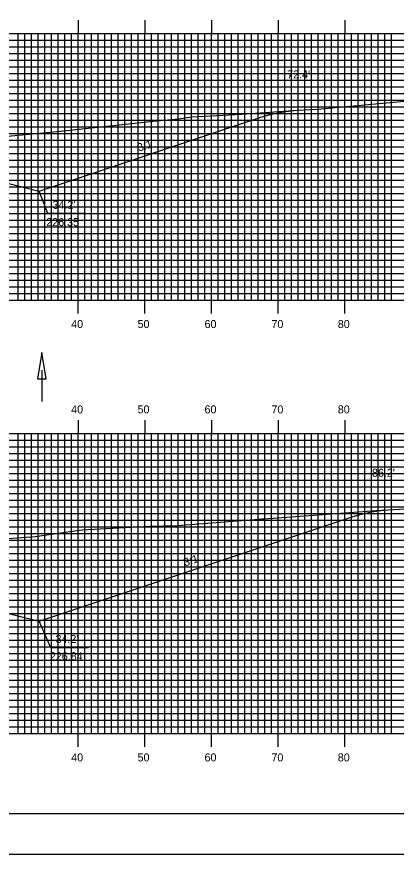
# Model space of a CAD drawing. Extents: x 1818457 to 1818800, y 442591 to 442811.
# Drawn here: x 1818653.4 to 1818710.4, y 442590.5 to 442716.2 of the extents above; entities that cross this region are included whole.
import ezdxf

# ---------------------------------------------------------------- set-up
doc = ezdxf.new("R2010")
doc.units = 0
for name, color, linetype in [('ANNOTATION', 7, 'Continuous'), ('BORDER', 7, 'Continuous'), ('D_Drainage_Ditch_Line', 7, 'Continuous'), ('D_Roadway_Centerline', 7, 'Continuous'), ('D_Roadway_SlopeLines', 7, 'Continuous'), ('D_Text_Standard', 7, 'Continuous'), ('H_V ANNOTATION', 7, 'Continuous'), ('MAJOR', 7, 'Continuous'), ('MINOR', 7, 'Continuous'), ('PLOT BOUNDARY', 7, 'Continuous'), ('S_Roadway_Centerline', 7, 'Continuous')]:
    doc.layers.add(name, color=color, linetype=linetype)

msp = doc.modelspace()

# ---------------------------------------------------------------- linework, layer by layer
at = {"layer": 'ANNOTATION'}
for points in [[(1818663.78, 442686.63), (1818658.09, 442686.63), (1818656.81, 442690.02)], [(1818664.23, 442621.52), (1818658.54, 442621.52), (1818656.81, 442625.5)]]:
    msp.add_lwpolyline(points, dxfattribs=at)
at = {"layer": 'BORDER'}
msp.add_lwpolyline([(1818473.04, 442596.67), (1818793.04, 442596.67), (1818793.04, 442806.67), (1818473.04, 442806.67)], close=True, dxfattribs=at)
at = {"layer": 'D_Drainage_Ditch_Line'}
msp.add_line((1818657.21, 442663.17), (1818657.21, 442658.47), dxfattribs=at)
msp.add_lwpolyline([(1818656.55, 442661.86), (1818657.87, 442661.86), (1818657.21, 442665.8)], close=True, dxfattribs=at)
at = {"layer": 'D_Roadway_Centerline'}
for points in [[(1818584.45, 442689.01), (1818590.64, 442690.56), (1818592.46, 442691.02), (1818602.64, 442693.56), (1818610.64, 442693.88), (1818622.64, 442694.12), (1818634.64, 442693.88), (1818642.64, 442693.56), (1818652.81, 442691.02), (1818656.81, 442690.02), (1818690.05, 442701.1), (1818691.3, 442701.47), (1818692.55, 442701.76), (1818693.8, 442701.97), (1818695.05, 442702.1)], [(1818576.1, 442628.49), (1818577.35, 442628.57), (1818578.6, 442628.51), (1818579.85, 442628.3), (1818581.1, 442627.96), (1818588.46, 442625.5), (1818592.46, 442626.5), (1818602.64, 442629.05), (1818610.64, 442629.37), (1818622.64, 442629.61), (1818634.64, 442629.37), (1818642.64, 442629.05), (1818652.81, 442626.5), (1818656.81, 442625.5), (1818703.88, 442641.19), (1818705.13, 442641.57), (1818706.38, 442641.86), (1818707.63, 442642.06), (1818708.88, 442642.19)]]:
    msp.add_lwpolyline(points, dxfattribs=at)
at = {"layer": 'D_Roadway_SlopeLines'}
for points in [[(1818656.81, 442690.02), (1818690.05, 442701.1), (1818691.3, 442701.47), (1818692.55, 442701.76), (1818693.8, 442701.97), (1818695.05, 442702.1)], [(1818642.64, 442693.56), (1818656.81, 442690.02)], [(1818656.81, 442625.5), (1818703.88, 442641.19), (1818705.13, 442641.57), (1818706.38, 442641.86), (1818707.63, 442642.06), (1818708.88, 442642.19)], [(1818642.64, 442629.05), (1818656.81, 442625.5)]]:
    msp.add_lwpolyline(points, dxfattribs=at)
at = {"layer": 'MAJOR'}
for p, q in [((1818662.64, 442715.67), (1818662.64, 442713.67)), ((1818672.64, 442715.67), (1818672.64, 442713.67)), ((1818682.64, 442715.67), (1818682.64, 442713.67)), ((1818692.64, 442715.67), (1818692.64, 442713.67)), ((1818702.64, 442715.67), (1818702.64, 442713.67)), ((1818482.64, 442713.67), (1818762.64, 442713.67)), ((1818482.64, 442713.67), (1818762.64, 442713.67)), ((1818662.64, 442673.67), (1818662.64, 442713.67)), ((1818672.64, 442673.67), (1818672.64, 442713.67)), ((1818682.64, 442673.67), (1818682.64, 442713.67)), ((1818692.64, 442673.67), (1818692.64, 442713.67)), ((1818702.64, 442673.67), (1818702.64, 442713.67)), ((1818482.64, 442708.67), (1818762.64, 442708.67)), ((1818482.64, 442703.67), (1818762.64, 442703.67)), ((1818482.64, 442698.67), (1818762.64, 442698.67)), ((1818482.64, 442693.67), (1818762.64, 442693.67)), ((1818482.64, 442688.67), (1818762.64, 442688.67)), ((1818482.64, 442683.67), (1818762.64, 442683.67)), ((1818482.64, 442678.67), (1818762.64, 442678.67)), ((1818482.64, 442673.67), (1818762.64, 442673.67)), ((1818482.64, 442673.67), (1818762.64, 442673.67)), ((1818662.64, 442671.66), (1818662.64, 442673.67)), ((1818672.64, 442671.66), (1818672.64, 442673.67)), ((1818682.64, 442671.66), (1818682.64, 442673.67)), ((1818692.64, 442671.66), (1818692.64, 442673.67)), ((1818702.64, 442671.66), (1818702.64, 442673.67)), ((1818662.64, 442655.67), (1818662.64, 442653.67)), ((1818672.64, 442655.67), (1818672.64, 442653.67)), ((1818682.64, 442655.67), (1818682.64, 442653.67)), ((1818692.64, 442655.67), (1818692.64, 442653.67)), ((1818702.64, 442655.67), (1818702.64, 442653.67)), ((1818482.64, 442653.67), (1818762.64, 442653.67)), ((1818482.64, 442653.67), (1818762.64, 442653.67)), ((1818662.64, 442608.67), (1818662.64, 442653.67)), ((1818672.64, 442608.67), (1818672.64, 442653.67)), ((1818682.64, 442608.67), (1818682.64, 442653.67)), ((1818692.64, 442608.67), (1818692.64, 442653.67)), ((1818702.64, 442608.67), (1818702.64, 442653.67)), ((1818482.64, 442648.67), (1818762.64, 442648.67)), ((1818482.64, 442643.67), (1818762.64, 442643.67)), ((1818482.64, 442638.67), (1818762.64, 442638.67)), ((1818482.64, 442633.67), (1818762.64, 442633.67)), ((1818482.64, 442628.67), (1818762.64, 442628.67)), ((1818482.64, 442623.67), (1818762.64, 442623.67)), ((1818482.64, 442618.67), (1818762.64, 442618.67)), ((1818482.64, 442613.67), (1818762.64, 442613.67)), ((1818482.64, 442608.67), (1818762.64, 442608.67)), ((1818482.64, 442608.67), (1818762.64, 442608.67)), ((1818662.64, 442606.66), (1818662.64, 442608.67)), ((1818672.64, 442606.66), (1818672.64, 442608.67)), ((1818682.64, 442606.66), (1818682.64, 442608.67)), ((1818692.64, 442606.66), (1818692.64, 442608.67)), ((1818702.64, 442606.66), (1818702.64, 442608.67))]:
    msp.add_line(p, q, dxfattribs=at)
at = {"layer": 'MINOR'}
for p, q in [((1818653.64, 442673.67), (1818653.64, 442713.67)), ((1818654.64, 442673.67), (1818654.64, 442713.67)), ((1818655.64, 442673.67), (1818655.64, 442713.67)), ((1818656.64, 442673.67), (1818656.64, 442713.67)), ((1818657.64, 442673.67), (1818657.64, 442713.67)), ((1818658.64, 442673.67), (1818658.64, 442713.67)), ((1818659.64, 442673.67), (1818659.64, 442713.67)), ((1818660.64, 442673.67), (1818660.64, 442713.67)), ((1818661.64, 442673.67), (1818661.64, 442713.67)), ((1818663.64, 442673.67), (1818663.64, 442713.67)), ((1818664.64, 442673.67), (1818664.64, 442713.67)), ((1818665.64, 442673.67), (1818665.64, 442713.67)), ((1818666.64, 442673.67), (1818666.64, 442713.67)), ((1818667.64, 442673.67), (1818667.64, 442713.67)), ((1818668.64, 442673.67), (1818668.64, 442713.67)), ((1818669.64, 442673.67), (1818669.64, 442713.67)), ((1818670.64, 442673.67), (1818670.64, 442713.67)), ((1818671.64, 442673.67), (1818671.64, 442713.67)), ((1818673.64, 442673.67), (1818673.64, 442713.67)), ((1818674.64, 442673.67), (1818674.64, 442713.67)), ((1818675.64, 442673.67), (1818675.64, 442713.67)), ((1818676.64, 442673.67), (1818676.64, 442713.67)), ((1818677.64, 442673.67), (1818677.64, 442713.67)), ((1818678.64, 442673.67), (1818678.64, 442713.67)), ((1818679.64, 442673.67), (1818679.64, 442713.67)), ((1818680.64, 442673.67), (1818680.64, 442713.67)), ((1818681.64, 442673.67), (1818681.64, 442713.67)), ((1818683.64, 442673.67), (1818683.64, 442713.67)), ((1818684.64, 442673.67), (1818684.64, 442713.67)), ((1818685.64, 442673.67), (1818685.64, 442713.67)), ((1818686.64, 442673.67), (1818686.64, 442713.67)), ((1818687.64, 442673.67), (1818687.64, 442713.67)), ((1818688.64, 442673.67), (1818688.64, 442713.67)), ((1818689.64, 442673.67), (1818689.64, 442713.67)), ((1818690.64, 442673.67), (1818690.64, 442713.67)), ((1818691.64, 442673.67), (1818691.64, 442713.67)), ((1818693.64, 442673.67), (1818693.64, 442713.67)), ((1818694.64, 442673.67), (1818694.64, 442713.67)), ((1818695.64, 442673.67), (1818695.64, 442713.67)), ((1818696.64, 442673.67), (1818696.64, 442713.67)), ((1818697.64, 442673.67), (1818697.64, 442713.67)), ((1818698.64, 442673.67), (1818698.64, 442713.67)), ((1818699.64, 442673.67), (1818699.64, 442713.67)), ((1818700.64, 442673.67), (1818700.64, 442713.67)), ((1818701.64, 442673.67), (1818701.64, 442713.67)), ((1818703.64, 442673.67), (1818703.64, 442713.67)), ((1818704.64, 442673.67), (1818704.64, 442713.67)), ((1818705.64, 442673.67), (1818705.64, 442713.67)), ((1818706.64, 442673.67), (1818706.64, 442713.67)), ((1818707.64, 442673.67), (1818707.64, 442713.67)), ((1818708.64, 442673.67), (1818708.64, 442713.67)), ((1818709.64, 442673.67), (1818709.64, 442713.67)), ((1818482.64, 442712.67), (1818762.64, 442712.67)), ((1818482.64, 442711.67), (1818762.64, 442711.67)), ((1818482.64, 442710.67), (1818762.64, 442710.67)), ((1818482.64, 442709.67), (1818762.64, 442709.67)), ((1818482.64, 442707.67), (1818762.64, 442707.67)), ((1818482.64, 442706.67), (1818762.64, 442706.67)), ((1818482.64, 442705.67), (1818762.64, 442705.67)), ((1818482.64, 442704.67), (1818762.64, 442704.67)), ((1818482.64, 442702.67), (1818762.64, 442702.67)), ((1818482.64, 442701.67), (1818762.64, 442701.67)), ((1818482.64, 442700.67), (1818762.64, 442700.67)), ((1818482.64, 442699.67), (1818762.64, 442699.67)), ((1818482.64, 442697.67), (1818762.64, 442697.67)), ((1818482.64, 442696.67), (1818762.64, 442696.67)), ((1818482.64, 442695.67), (1818762.64, 442695.67)), ((1818482.64, 442694.67), (1818762.64, 442694.67)), ((1818482.64, 442692.67), (1818762.64, 442692.67)), ((1818482.64, 442691.67), (1818762.64, 442691.67)), ((1818482.64, 442690.67), (1818762.64, 442690.67)), ((1818482.64, 442689.67), (1818762.64, 442689.67)), ((1818482.64, 442687.67), (1818762.64, 442687.67)), ((1818482.64, 442686.67), (1818762.64, 442686.67)), ((1818482.64, 442685.67), (1818762.64, 442685.67)), ((1818482.64, 442684.67), (1818762.64, 442684.67)), ((1818482.64, 442682.67), (1818762.64, 442682.67)), ((1818482.64, 442681.67), (1818762.64, 442681.67)), ((1818482.64, 442680.67), (1818762.64, 442680.67)), ((1818482.64, 442679.67), (1818762.64, 442679.67)), ((1818482.64, 442677.67), (1818762.64, 442677.67)), ((1818482.64, 442676.67), (1818762.64, 442676.67)), ((1818482.64, 442675.67), (1818762.64, 442675.67)), ((1818482.64, 442674.67), (1818762.64, 442674.67)), ((1818653.64, 442608.67), (1818653.64, 442653.67)), ((1818654.64, 442608.67), (1818654.64, 442653.67)), ((1818655.64, 442608.67), (1818655.64, 442653.67)), ((1818656.64, 442608.67), (1818656.64, 442653.67)), ((1818657.64, 442608.67), (1818657.64, 442653.67)), ((1818658.64, 442608.67), (1818658.64, 442653.67)), ((1818659.64, 442608.67), (1818659.64, 442653.67)), ((1818660.64, 442608.67), (1818660.64, 442653.67)), ((1818661.64, 442608.67), (1818661.64, 442653.67)), ((1818663.64, 442608.67), (1818663.64, 442653.67)), ((1818664.64, 442608.67), (1818664.64, 442653.67)), ((1818665.64, 442608.67), (1818665.64, 442653.67)), ((1818666.64, 442608.67), (1818666.64, 442653.67)), ((1818667.64, 442608.67), (1818667.64, 442653.67)), ((1818668.64, 442608.67), (1818668.64, 442653.67)), ((1818669.64, 442608.67), (1818669.64, 442653.67)), ((1818670.64, 442608.67), (1818670.64, 442653.67)), ((1818671.64, 442608.67), (1818671.64, 442653.67)), ((1818673.64, 442608.67), (1818673.64, 442653.67)), ((1818674.64, 442608.67), (1818674.64, 442653.67)), ((1818675.64, 442608.67), (1818675.64, 442653.67)), ((1818676.64, 442608.67), (1818676.64, 442653.67)), ((1818677.64, 442608.67), (1818677.64, 442653.67)), ((1818678.64, 442608.67), (1818678.64, 442653.67)), ((1818679.64, 442608.67), (1818679.64, 442653.67)), ((1818680.64, 442608.67), (1818680.64, 442653.67)), ((1818681.64, 442608.67), (1818681.64, 442653.67)), ((1818683.64, 442608.67), (1818683.64, 442653.67)), ((1818684.64, 442608.67), (1818684.64, 442653.67)), ((1818685.64, 442608.67), (1818685.64, 442653.67)), ((1818686.64, 442608.67), (1818686.64, 442653.67)), ((1818687.64, 442608.67), (1818687.64, 442653.67)), ((1818688.64, 442608.67), (1818688.64, 442653.67)), ((1818689.64, 442608.67), (1818689.64, 442653.67)), ((1818690.64, 442608.67), (1818690.64, 442653.67)), ((1818691.64, 442608.67), (1818691.64, 442653.67)), ((1818693.64, 442608.67), (1818693.64, 442653.67)), ((1818694.64, 442608.67), (1818694.64, 442653.67)), ((1818695.64, 442608.67), (1818695.64, 442653.67)), ((1818696.64, 442608.67), (1818696.64, 442653.67)), ((1818697.64, 442608.67), (1818697.64, 442653.67)), ((1818698.64, 442608.67), (1818698.64, 442653.67)), ((1818699.64, 442608.67), (1818699.64, 442653.67)), ((1818700.64, 442608.67), (1818700.64, 442653.67)), ((1818701.64, 442608.67), (1818701.64, 442653.67)), ((1818703.64, 442608.67), (1818703.64, 442653.67)), ((1818704.64, 442608.67), (1818704.64, 442653.67)), ((1818705.64, 442608.67), (1818705.64, 442653.67)), ((1818706.64, 442608.67), (1818706.64, 442653.67)), ((1818707.64, 442608.67), (1818707.64, 442653.67)), ((1818708.64, 442608.67), (1818708.64, 442653.67)), ((1818709.64, 442608.67), (1818709.64, 442653.67)), ((1818482.64, 442652.67), (1818762.64, 442652.67)), ((1818482.64, 442651.67), (1818762.64, 442651.67)), ((1818482.64, 442650.67), (1818762.64, 442650.67)), ((1818482.64, 442649.67), (1818762.64, 442649.67)), ((1818482.64, 442647.67), (1818762.64, 442647.67)), ((1818482.64, 442646.67), (1818762.64, 442646.67)), ((1818482.64, 442645.67), (1818762.64, 442645.67)), ((1818482.64, 442644.67), (1818762.64, 442644.67)), ((1818482.64, 442642.67), (1818762.64, 442642.67)), ((1818482.64, 442641.67), (1818762.64, 442641.67)), ((1818482.64, 442640.67), (1818762.64, 442640.67)), ((1818482.64, 442639.67), (1818762.64, 442639.67)), ((1818482.64, 442637.67), (1818762.64, 442637.67)), ((1818482.64, 442636.67), (1818762.64, 442636.67)), ((1818482.64, 442635.67), (1818762.64, 442635.67)), ((1818482.64, 442634.67), (1818762.64, 442634.67)), ((1818482.64, 442632.67), (1818762.64, 442632.67)), ((1818482.64, 442631.67), (1818762.64, 442631.67)), ((1818482.64, 442630.67), (1818762.64, 442630.67)), ((1818482.64, 442629.67), (1818762.64, 442629.67)), ((1818482.64, 442627.67), (1818762.64, 442627.67)), ((1818482.64, 442626.67), (1818762.64, 442626.67)), ((1818482.64, 442625.67), (1818762.64, 442625.67)), ((1818482.64, 442624.67), (1818762.64, 442624.67)), ((1818482.64, 442622.67), (1818762.64, 442622.67)), ((1818482.64, 442621.67), (1818762.64, 442621.67)), ((1818482.64, 442620.67), (1818762.64, 442620.67)), ((1818482.64, 442619.67), (1818762.64, 442619.67)), ((1818482.64, 442617.67), (1818762.64, 442617.67)), ((1818482.64, 442616.67), (1818762.64, 442616.67)), ((1818482.64, 442615.67), (1818762.64, 442615.67)), ((1818482.64, 442614.67), (1818762.64, 442614.67)), ((1818482.64, 442612.67), (1818762.64, 442612.67)), ((1818482.64, 442611.67), (1818762.64, 442611.67)), ((1818482.64, 442610.67), (1818762.64, 442610.67)), ((1818482.64, 442609.67), (1818762.64, 442609.67))]:
    msp.add_line(p, q, dxfattribs=at)
at = {"layer": 'PLOT BOUNDARY'}
msp.add_lwpolyline([(1818456.85, 442590.55), (1818796.85, 442590.55), (1818796.85, 442810.55), (1818456.85, 442810.55)], close=True, dxfattribs=at)
at = {"layer": 'S_Roadway_Centerline'}
for points in [[(1818558.62, 442686.34), (1818592.64, 442689.86), (1818624.71, 442694.18), (1818626.66, 442694.46), (1818628.43, 442694.76), (1818643.28, 442696.68), (1818652.59, 442698.28), (1818659.99, 442699.02), (1818673.9, 442700.48), (1818677.73, 442700.87), (1818679.7, 442701.16), (1818687.16, 442701.55), (1818695.53, 442702.14), (1818698.53, 442702.3), (1818712.14, 442703.56), (1818720.25, 442703.99), (1818728.64, 442704.61), (1818742.98, 442705.29), (1818747.44, 442705.45), (1818752.79, 442705.66), (1818759.89, 442705.98), (1818762.64, 442706.21)], [(1818572.16, 442628.02), (1818582.15, 442629.22), (1818588.63, 442629.97), (1818597.53, 442631.66), (1818606.3, 442632.63), (1818610.55, 442633.07), (1818626.97, 442635.25), (1818637.03, 442636.68), (1818639.51, 442636.95), (1818644.55, 442637.34), (1818656.22, 442638.21), (1818663.19, 442639.18), (1818673.33, 442639.73), (1818677.55, 442639.86), (1818689.08, 442640.76), (1818690.2, 442640.85), (1818690.56, 442640.87), (1818704, 442641.84), (1818707.32, 442642.1), (1818713.43, 442642.45)]]:
    msp.add_lwpolyline(points, dxfattribs=at)

# ---------------------------------------------------------------- texts
at = {"layer": 'ANNOTATION'}
for p in [(1818671.77, 442695.91), (1818678.68, 442633.7)]:
    msp.add_text('3:1', height=1.2, rotation=18.4348, dxfattribs=at).set_placement(p)
for s, p in [("34.2'", (1818658.82, 442687.35)), ('226.35', (1818657.88, 442684.75)), ("34.2'", (1818659.27, 442622.25)), ('226.84', (1818658.42, 442619.65))]:
    msp.add_text(s, height=1.2, dxfattribs=at).set_placement(p)
at = {"layer": 'D_Text_Standard'}
for s, p in [("72.4'", (1818694, 442706.91)), ("86.2'", (1818706.72, 442647.16))]:
    msp.add_text(s, height=1.2, dxfattribs=at).set_placement(p)
at = {"layer": 'H_V ANNOTATION'}
for s, p in [('40', (1818661.61, 442669.47)), ('50', (1818671.57, 442669.47)), ('60', (1818681.61, 442669.47)), ('70', (1818691.64, 442669.47)), ('80', (1818701.59, 442669.47)), ('40', (1818661.61, 442656.67)), ('50', (1818671.57, 442656.67)), ('60', (1818681.61, 442656.67)), ('70', (1818691.64, 442656.67)), ('80', (1818701.59, 442656.67)), ('40', (1818661.61, 442604.47)), ('50', (1818671.57, 442604.47)), ('60', (1818681.61, 442604.47)), ('70', (1818691.64, 442604.47)), ('80', (1818701.59, 442604.47))]:
    msp.add_text(s, height=1.2, dxfattribs=at).set_placement(p)

doc.saveas('drawing.dxf')
